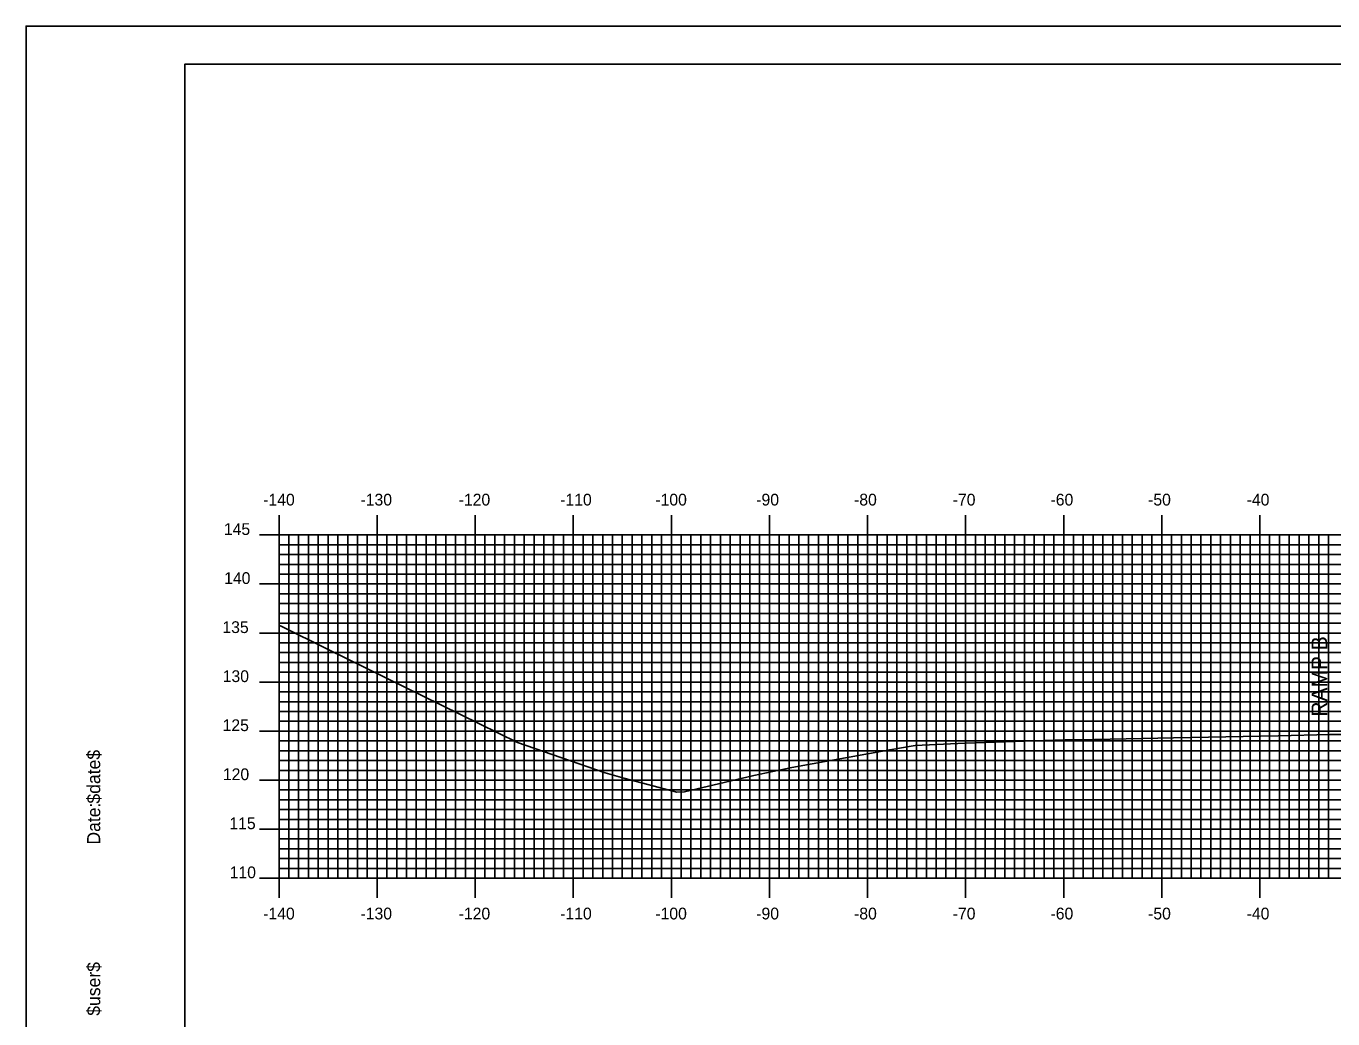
# Model space of a CAD drawing. Extents: x 853107 to 853450, y 366605 to 366825.
# Drawn here: x 853106.7 to 853239.9, y 366723.7 to 366824.9 of the extents above; entities that cross this region are included whole.
import ezdxf

# ---------------------------------------------------------------- set-up
doc = ezdxf.new("R2010")
doc.units = 0
for name, color, linetype in [('ANNOTATION', 7, 'Continuous'), ('BORDER', 7, 'Continuous'), ('H_V ANNOTATION', 7, 'Continuous'), ('M_Roadway_Centerline', 7, 'Continuous'), ('MAJOR', 7, 'Continuous'), ('MINOR', 7, 'Continuous'), ('PLOT BOUNDARY', 7, 'Continuous'), ('S_Roadway_Centerline', 7, 'Continuous')]:
    doc.layers.add(name, color=color, linetype=linetype)

msp = doc.modelspace()

# ---------------------------------------------------------------- linework, layer by layer
at = {"layer": 'BORDER'}
msp.add_lwpolyline([(853122.9, 366611.06), (853442.9, 366611.06), (853442.9, 366821.06), (853122.9, 366821.06)], close=True, dxfattribs=at)
at = {"layer": 'MAJOR'}
for p, q in [((853132.5, 366775.06), (853132.5, 366773.06)), ((853142.5, 366775.06), (853142.5, 366773.06)), ((853152.5, 366775.06), (853152.5, 366773.06)), ((853162.5, 366775.06), (853162.5, 366773.06)), ((853172.5, 366775.06), (853172.5, 366773.06)), ((853182.5, 366775.06), (853182.5, 366773.06)), ((853192.5, 366775.06), (853192.5, 366773.06)), ((853202.5, 366775.06), (853202.5, 366773.06)), ((853212.5, 366775.06), (853212.5, 366773.06)), ((853222.5, 366775.06), (853222.5, 366773.06)), ((853232.5, 366775.06), (853232.5, 366773.06)), ((853130.5, 366773.06), (853132.5, 366773.06)), ((853132.5, 366773.06), (853412.5, 366773.06)), ((853132.5, 366738.06), (853132.5, 366773.06)), ((853132.5, 366738.06), (853132.5, 366773.06)), ((853132.5, 366773.06), (853412.5, 366773.06)), ((853142.5, 366738.06), (853142.5, 366773.06)), ((853152.5, 366738.06), (853152.5, 366773.06)), ((853162.5, 366738.06), (853162.5, 366773.06)), ((853172.5, 366738.06), (853172.5, 366773.06)), ((853182.5, 366738.06), (853182.5, 366773.06)), ((853192.5, 366738.06), (853192.5, 366773.06)), ((853202.5, 366738.06), (853202.5, 366773.06)), ((853212.5, 366738.06), (853212.5, 366773.06)), ((853222.5, 366738.06), (853222.5, 366773.06)), ((853232.5, 366738.06), (853232.5, 366773.06)), ((853130.5, 366768.06), (853132.5, 366768.06)), ((853132.5, 366768.06), (853412.5, 366768.06)), ((853130.5, 366763.06), (853132.5, 366763.06)), ((853132.5, 366763.06), (853412.5, 366763.06)), ((853130.5, 366758.06), (853132.5, 366758.06)), ((853132.5, 366758.06), (853412.5, 366758.06)), ((853130.5, 366753.06), (853132.5, 366753.06)), ((853132.5, 366753.06), (853412.5, 366753.06)), ((853130.5, 366748.06), (853132.5, 366748.06)), ((853132.5, 366748.06), (853412.5, 366748.06)), ((853130.5, 366743.06), (853132.5, 366743.06)), ((853132.5, 366743.06), (853412.5, 366743.06)), ((853130.5, 366738.06), (853132.5, 366738.06)), ((853132.5, 366738.06), (853412.5, 366738.06)), ((853132.5, 366738.06), (853412.5, 366738.06)), ((853132.5, 366736.05), (853132.5, 366738.06)), ((853142.5, 366736.05), (853142.5, 366738.06)), ((853152.5, 366736.05), (853152.5, 366738.06)), ((853162.5, 366736.05), (853162.5, 366738.06)), ((853172.5, 366736.05), (853172.5, 366738.06)), ((853182.5, 366736.05), (853182.5, 366738.06)), ((853192.5, 366736.05), (853192.5, 366738.06)), ((853202.5, 366736.05), (853202.5, 366738.06)), ((853212.5, 366736.05), (853212.5, 366738.06)), ((853222.5, 366736.05), (853222.5, 366738.06)), ((853232.5, 366736.05), (853232.5, 366738.06))]:
    msp.add_line(p, q, dxfattribs=at)
at = {"layer": 'MINOR'}
for p, q in [((853133.5, 366738.06), (853133.5, 366773.06)), ((853134.5, 366738.06), (853134.5, 366773.06)), ((853135.5, 366738.06), (853135.5, 366773.06)), ((853136.5, 366738.06), (853136.5, 366773.06)), ((853137.5, 366738.06), (853137.5, 366773.06)), ((853138.5, 366738.06), (853138.5, 366773.06)), ((853139.5, 366738.06), (853139.5, 366773.06)), ((853140.5, 366738.06), (853140.5, 366773.06)), ((853141.5, 366738.06), (853141.5, 366773.06)), ((853143.5, 366738.06), (853143.5, 366773.06)), ((853144.5, 366738.06), (853144.5, 366773.06)), ((853145.5, 366738.06), (853145.5, 366773.06)), ((853146.5, 366738.06), (853146.5, 366773.06)), ((853147.5, 366738.06), (853147.5, 366773.06)), ((853148.5, 366738.06), (853148.5, 366773.06)), ((853149.5, 366738.06), (853149.5, 366773.06)), ((853150.5, 366738.06), (853150.5, 366773.06)), ((853151.5, 366738.06), (853151.5, 366773.06)), ((853153.5, 366738.06), (853153.5, 366773.06)), ((853154.5, 366738.06), (853154.5, 366773.06)), ((853155.5, 366738.06), (853155.5, 366773.06)), ((853156.5, 366738.06), (853156.5, 366773.06)), ((853157.5, 366738.06), (853157.5, 366773.06)), ((853158.5, 366738.06), (853158.5, 366773.06)), ((853159.5, 366738.06), (853159.5, 366773.06)), ((853160.5, 366738.06), (853160.5, 366773.06)), ((853161.5, 366738.06), (853161.5, 366773.06)), ((853163.5, 366738.06), (853163.5, 366773.06)), ((853164.5, 366738.06), (853164.5, 366773.06)), ((853165.5, 366738.06), (853165.5, 366773.06)), ((853166.5, 366738.06), (853166.5, 366773.06)), ((853167.5, 366738.06), (853167.5, 366773.06)), ((853168.5, 366738.06), (853168.5, 366773.06)), ((853169.5, 366738.06), (853169.5, 366773.06)), ((853170.5, 366738.06), (853170.5, 366773.06)), ((853171.5, 366738.06), (853171.5, 366773.06)), ((853173.5, 366738.06), (853173.5, 366773.06)), ((853174.5, 366738.06), (853174.5, 366773.06)), ((853175.5, 366738.06), (853175.5, 366773.06)), ((853176.5, 366738.06), (853176.5, 366773.06)), ((853177.5, 366738.06), (853177.5, 366773.06)), ((853178.5, 366738.06), (853178.5, 366773.06)), ((853179.5, 366738.06), (853179.5, 366773.06)), ((853180.5, 366738.06), (853180.5, 366773.06)), ((853181.5, 366738.06), (853181.5, 366773.06)), ((853183.5, 366738.06), (853183.5, 366773.06)), ((853184.5, 366738.06), (853184.5, 366773.06)), ((853185.5, 366738.06), (853185.5, 366773.06)), ((853186.5, 366738.06), (853186.5, 366773.06)), ((853187.5, 366738.06), (853187.5, 366773.06)), ((853188.5, 366738.06), (853188.5, 366773.06)), ((853189.5, 366738.06), (853189.5, 366773.06)), ((853190.5, 366738.06), (853190.5, 366773.06)), ((853191.5, 366738.06), (853191.5, 366773.06)), ((853193.5, 366738.06), (853193.5, 366773.06)), ((853194.5, 366738.06), (853194.5, 366773.06)), ((853195.5, 366738.06), (853195.5, 366773.06)), ((853196.5, 366738.06), (853196.5, 366773.06)), ((853197.5, 366738.06), (853197.5, 366773.06)), ((853198.5, 366738.06), (853198.5, 366773.06)), ((853199.5, 366738.06), (853199.5, 366773.06)), ((853200.5, 366738.06), (853200.5, 366773.06)), ((853201.5, 366738.06), (853201.5, 366773.06)), ((853203.5, 366738.06), (853203.5, 366773.06)), ((853204.5, 366738.06), (853204.5, 366773.06)), ((853205.5, 366738.06), (853205.5, 366773.06)), ((853206.5, 366738.06), (853206.5, 366773.06)), ((853207.5, 366738.06), (853207.5, 366773.06)), ((853208.5, 366738.06), (853208.5, 366773.06)), ((853209.5, 366738.06), (853209.5, 366773.06)), ((853210.5, 366738.06), (853210.5, 366773.06)), ((853211.5, 366738.06), (853211.5, 366773.06)), ((853213.5, 366738.06), (853213.5, 366773.06)), ((853214.5, 366738.06), (853214.5, 366773.06)), ((853215.5, 366738.06), (853215.5, 366773.06)), ((853216.5, 366738.06), (853216.5, 366773.06)), ((853217.5, 366738.06), (853217.5, 366773.06)), ((853218.5, 366738.06), (853218.5, 366773.06)), ((853219.5, 366738.06), (853219.5, 366773.06)), ((853220.5, 366738.06), (853220.5, 366773.06)), ((853221.5, 366738.06), (853221.5, 366773.06)), ((853223.5, 366738.06), (853223.5, 366773.06)), ((853224.5, 366738.06), (853224.5, 366773.06)), ((853225.5, 366738.06), (853225.5, 366773.06)), ((853226.5, 366738.06), (853226.5, 366773.06)), ((853227.5, 366738.06), (853227.5, 366773.06)), ((853228.5, 366738.06), (853228.5, 366773.06)), ((853229.5, 366738.06), (853229.5, 366773.06)), ((853230.5, 366738.06), (853230.5, 366773.06)), ((853231.5, 366738.06), (853231.5, 366773.06)), ((853233.5, 366738.06), (853233.5, 366773.06)), ((853234.5, 366738.06), (853234.5, 366773.06)), ((853235.5, 366738.06), (853235.5, 366773.06)), ((853236.5, 366738.06), (853236.5, 366773.06)), ((853237.5, 366738.06), (853237.5, 366773.06)), ((853238.5, 366738.06), (853238.5, 366773.06)), ((853239.5, 366738.06), (853239.5, 366773.06)), ((853132.5, 366772.06), (853412.5, 366772.06)), ((853132.5, 366772.06), (853134.51, 366772.06)), ((853132.5, 366771.06), (853412.5, 366771.06)), ((853132.5, 366771.06), (853134.51, 366771.06)), ((853132.5, 366770.06), (853412.5, 366770.06)), ((853132.5, 366770.06), (853134.51, 366770.06)), ((853132.5, 366769.06), (853412.5, 366769.06)), ((853132.5, 366769.06), (853134.51, 366769.06)), ((853132.5, 366767.06), (853412.5, 366767.06)), ((853132.5, 366767.06), (853134.51, 366767.06)), ((853132.5, 366766.06), (853412.5, 366766.06)), ((853132.5, 366766.06), (853134.51, 366766.06)), ((853132.5, 366765.06), (853412.5, 366765.06)), ((853132.5, 366765.06), (853134.51, 366765.06)), ((853132.5, 366764.06), (853412.5, 366764.06)), ((853132.5, 366764.06), (853134.51, 366764.06)), ((853132.5, 366762.06), (853412.5, 366762.06)), ((853132.5, 366762.06), (853134.51, 366762.06)), ((853132.5, 366761.06), (853412.5, 366761.06)), ((853132.5, 366761.06), (853134.51, 366761.06)), ((853132.5, 366760.06), (853412.5, 366760.06)), ((853132.5, 366760.06), (853134.51, 366760.06)), ((853132.5, 366759.06), (853412.5, 366759.06)), ((853132.5, 366759.06), (853134.51, 366759.06)), ((853132.5, 366757.06), (853412.5, 366757.06)), ((853132.5, 366757.06), (853134.51, 366757.06)), ((853132.5, 366756.06), (853412.5, 366756.06)), ((853132.5, 366756.06), (853134.51, 366756.06)), ((853132.5, 366755.06), (853412.5, 366755.06)), ((853132.5, 366755.06), (853134.51, 366755.06)), ((853132.5, 366754.06), (853412.5, 366754.06)), ((853132.5, 366754.06), (853134.51, 366754.06)), ((853132.5, 366752.06), (853412.5, 366752.06)), ((853132.5, 366752.06), (853134.51, 366752.06)), ((853132.5, 366751.06), (853412.5, 366751.06)), ((853132.5, 366751.06), (853134.51, 366751.06)), ((853132.5, 366750.06), (853412.5, 366750.06)), ((853132.5, 366750.06), (853134.51, 366750.06)), ((853132.5, 366749.06), (853412.5, 366749.06)), ((853132.5, 366749.06), (853134.51, 366749.06)), ((853132.5, 366747.06), (853412.5, 366747.06)), ((853132.5, 366747.06), (853134.51, 366747.06)), ((853132.5, 366746.06), (853412.5, 366746.06)), ((853132.5, 366746.06), (853134.51, 366746.06)), ((853132.5, 366745.06), (853412.5, 366745.06)), ((853132.5, 366745.06), (853134.51, 366745.06)), ((853132.5, 366744.06), (853412.5, 366744.06)), ((853132.5, 366744.06), (853134.51, 366744.06)), ((853132.5, 366742.06), (853412.5, 366742.06)), ((853132.5, 366742.06), (853134.51, 366742.06)), ((853132.5, 366741.06), (853412.5, 366741.06)), ((853132.5, 366741.06), (853134.51, 366741.06)), ((853132.5, 366740.06), (853412.5, 366740.06)), ((853132.5, 366740.06), (853134.51, 366740.06)), ((853132.5, 366739.06), (853412.5, 366739.06)), ((853132.5, 366739.06), (853134.51, 366739.06))]:
    msp.add_line(p, q, dxfattribs=at)
at = {"layer": 'PLOT BOUNDARY'}
msp.add_lwpolyline([(853106.72, 366604.94), (853446.72, 366604.94), (853446.72, 366824.94), (853106.72, 366824.94)], close=True, dxfattribs=at)
at = {"layer": 'S_Roadway_Centerline'}
msp.add_lwpolyline([(853132.5, 366763.84), (853132.72, 366763.76), (853137.45, 366761.41), (853156.8, 366751.9), (853165.76, 366748.79), (853167.64, 366748.25), (853173.07, 366746.83), (853173.83, 366746.88), (853180.91, 366748.52), (853184.8, 366749.36), (853194.76, 366751.16), (853197.36, 366751.58), (853202.44, 366751.82), (853204.5, 366751.9), (853212.66, 366752.16), (853213.04, 366752.16), (853215.66, 366752.2), (853223.71, 366752.36), (853234.36, 366752.59), (853239.65, 366752.7), (853240.89, 366752.73)], dxfattribs=at)

# ---------------------------------------------------------------- texts
at = {"layer": 'ANNOTATION'}
msp.add_text('RAMP B', height=1.6, rotation=90, dxfattribs=at).set_placement((853239.37, 366754.53))
at = {"layer": 'BORDER'}
for s, p in [('$date$', (853114.27, 366745.67)), ('Date:', (853114.27, 366741.49)), ('$user$', (853114.27, 366724.04))]:
    msp.add_text(s, height=1.339, rotation=90, dxfattribs=at).set_placement(p)
at = {"layer": 'H_V ANNOTATION'}
for s, p in [('-140', (853130.89, 366776.06)), ('-130', (853140.81, 366776.06)), ('-120', (853150.82, 366776.06)), ('-110', (853161.17, 366776.06)), ('-100', (853170.87, 366776.06)), ('-90', (853181.16, 366776.06)), ('-80', (853191.13, 366776.06)), ('-70', (853201.19, 366776.06)), ('-60', (853211.16, 366776.06)), ('-50', (853221.11, 366776.06)), ('-40', (853231.16, 366776.06)), ('145', (853126.88, 366773.06)), ('140', (853126.91, 366768.06)), ('135', (853126.73, 366763.06)), ('130', (853126.76, 366758.06)), ('125', (853126.75, 366753.06)), ('120', (853126.78, 366748.06)), ('115', (853127.44, 366743.06)), ('110', (853127.47, 366738.06)), ('-140', (853130.89, 366733.86)), ('-130', (853140.81, 366733.86)), ('-120', (853150.82, 366733.86)), ('-110', (853161.17, 366733.86)), ('-100', (853170.87, 366733.86)), ('-90', (853181.16, 366733.86)), ('-80', (853191.13, 366733.86)), ('-70', (853201.19, 366733.86)), ('-60', (853211.16, 366733.86)), ('-50', (853221.11, 366733.86)), ('-40', (853231.16, 366733.86))]:
    msp.add_text(s, height=1.2, dxfattribs=at).set_placement(p)
at = {"layer": 'M_Roadway_Centerline'}
for s, p in [('C', (853212.66, 366752.16)), ('L', (853212.66, 366752.15))]:
    msp.add_text(s, height=0.0146, dxfattribs=at).set_placement(p)
at = {"layer": 'MAJOR'}
msp.add_text('-', height=0.012, dxfattribs=at).set_placement((853132.49, 366738.06))

doc.saveas('drawing.dxf')
